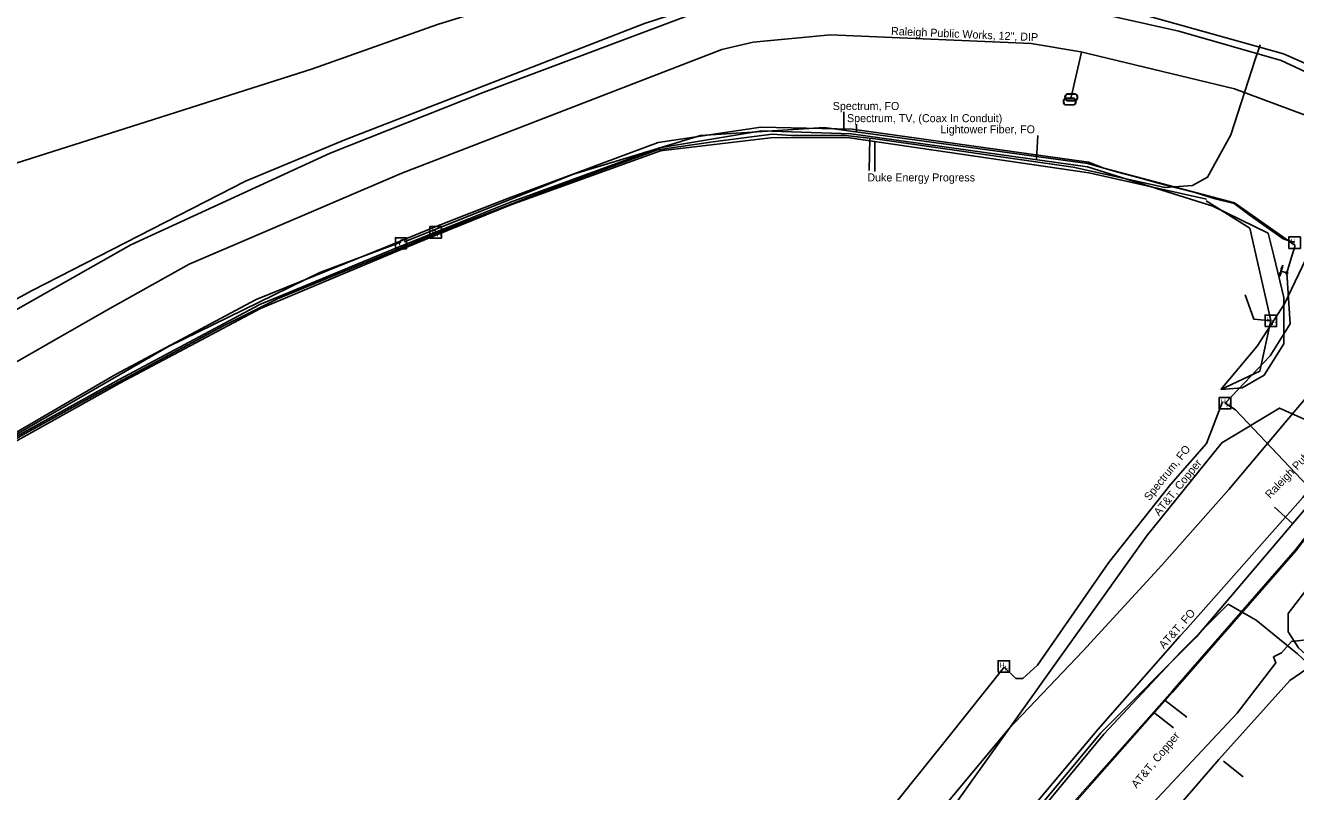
# Model space of a CAD drawing. Extents: x 2070721 to 2083039, y 729290 to 737883.
# Drawn here: x 2081248 to 2081883, y 734630 to 735013 of the extents above; entities that cross this region are included whole.
import ezdxf

# ---------------------------------------------------------------- set-up
doc = ezdxf.new("R2010")
doc.units = 0
for name, color, linetype in [('Cogo Default Point CELL', 7, 'Continuous'), ('Exist Utilities Gas UG Line SUE Cogo Point CELL', 7, 'Continuous'), ('Exist Utilities Gas UG Line SUE LOS B Cogo Comment', 7, 'Continuous'), ('Exist Utilities Gas UG Line SUE LOS B Cogo Number', 7, 'Continuous'), ('Exist Utilities Gas UG Line SUE LOS B Cogo Point CELL', 7, 'Continuous'), ('Exist Utilities Gas Valve CELL', 7, 'Continuous'), ('Exist Utilities Gas Valve Cogo Elevation', 7, 'Continuous'), ('Exist Utilities Other Unknown UG SUE Cogo Point CELL', 7, 'Continuous'), ('Exist Utilities Power Pole Cogo Elevation', 7, 'Continuous'), ('Exist Utilities Telephone UG Cable Cogo Point CELL', 7, 'Continuous'), ('Exist Utilities Telephone UG Cable SUE LOS C Cogo Comment', 7, 'Continuous'), ('Exist Utilities Telephone UG Cable SUE LOS C Cogo Elevation', 7, 'Continuous'), ('Exist Utilities Telephone UG FO Cogo Point CELL', 7, 'Continuous'), ('Exist Utilities Telephone UG FO SUE LOS B Cogo Number', 7, 'Continuous'), ('Exist Utilities TV Hand Hole CELL', 7, 'Continuous'), ('Exist Utilities TV Pedestal CELL', 7, 'Continuous'), ('Exist Utilities TV Pedestal Cogo Elevation', 7, 'Continuous'), ('Exist Utilities TV UG Cable Cogo Point CELL', 7, 'Continuous'), ('Exist Utilities TV UG Cable SUE LOS C Cogo Comment', 7, 'Continuous'), ('Exist Utilities TV UG Cable SUE LOS C Cogo Number', 7, 'Continuous'), ('Exist Utilities TV UG Cable SUE LOS C Cogo Point CELL', 7, 'Continuous'), ('Exist Utilities Water Manhole Cogo Elevation', 7, 'Continuous'), ('Exist Utilities Water Manhole Cogo Number', 7, 'Continuous'), ('Exist Utilities Water Meter CELL', 7, 'Continuous'), ('Exist Utilities Water Meter Cogo Number', 7, 'Continuous'), ('Exist Utilities Water UG Line SUE LOS B Cogo Elevation', 7, 'Continuous'), ('Exist Utilities Water UG Line SUE LOS B Cogo Number', 7, 'Continuous'), ('Exist Utilities Water Valve CELL', 7, 'Continuous')]:
    doc.layers.add(name, color=color, linetype=linetype)

msp = doc.modelspace()

# ---------------------------------------------------------------- linework, layer by layer
at = {"layer": 'Cogo Default Point CELL'}
msp.add_line((2081435.56, 734903.92), (2081435.56, 734903.92), dxfattribs=at)
msp.add_lwpolyline([(2081432.79, 734901.15), (2081438.33, 734901.15), (2081438.33, 734906.7), (2081432.79, 734906.7), (2081432.79, 734901.15)], dxfattribs=at)
at = {"layer": 'Exist Utilities Gas UG Line SUE LOS B Cogo Number'}
msp.add_line((2081656.86, 734960.96), (2081656.86, 734969.6), dxfattribs=at)
at = {"layer": 'Exist Utilities Gas Valve CELL'}
for p, q in [((2081669.9, 734956.32), (2081669.61, 734940.23)), ((2081672.4, 734954.58), (2081672.4, 734939.68)), ((2081846.67, 734645.35), (2081856.43, 734637.48))]:
    msp.add_line(p, q, dxfattribs=at)
at = {"layer": 'Exist Utilities Gas Valve Cogo Elevation'}
for p, q in [((2081811.7, 734669.77), (2081821.62, 734661.91)), ((2081817.5, 734675.55), (2081828.33, 734667.26))]:
    msp.add_line(p, q, dxfattribs=at)
at = {"layer": 'Exist Utilities Other Unknown UG SUE Cogo Point CELL'}
msp.add_line((2081663.14, 734959.52), (2081663.14, 734963.39), dxfattribs=at)
at = {"layer": 'Exist Utilities Power Pole Cogo Elevation'}
msp.add_lwpolyline([(2081225.5, 734796.32), (2081248.11, 734809.04), (2081287.63, 734830.88), (2081326.72, 734851.91), (2081347.2, 734862.89), (2081373.88, 734876.14), (2081398.46, 734886.3), (2081460.49, 734911.77), (2081509.14, 734930.55), (2081563.83, 734950.54), (2081592.79, 734954.64), (2081621.06, 734958.42), (2081630.74, 734957.65), (2081639.48, 734957.65), (2081657.7, 734957.65), (2081672.52, 734956.07), (2081771.45, 734941.91), (2081817.43, 734931.74), (2081831.08, 734932.73), (2081838.68, 734936.87), (2081850.29, 734958.08), (2081862.4, 734995.7), (2081864.93, 735002.95)], dxfattribs=at)
at = {"layer": 'Exist Utilities Telephone UG Cable Cogo Point CELL'}
for p, q in [((2081882.13, 734904.21), (2081882.13, 734904.21)), ((2081847.37, 734824.04), (2081847.37, 734824.04)), ((2081736.86, 734692.57), (2081736.86, 734692.57))]:
    msp.add_line(p, q, dxfattribs=at)
for points in [[(2081879.26, 734901.33), (2081885.01, 734901.33), (2081885.01, 734907.08), (2081879.26, 734907.08), (2081879.26, 734901.33)], [(2081844.5, 734821.17), (2081850.25, 734821.17), (2081850.25, 734826.92), (2081844.5, 734826.92), (2081844.5, 734821.17)], [(2081733.99, 734689.7), (2081739.74, 734689.7), (2081739.74, 734695.45), (2081733.99, 734695.45), (2081733.99, 734689.7)]]:
    msp.add_lwpolyline(points, dxfattribs=at)
at = {"layer": 'Exist Utilities Telephone UG Cable SUE LOS C Cogo Comment'}
msp.add_lwpolyline([(2081599.02, 734480.52), (2081638.91, 734537.92), (2081689.31, 734601.45), (2081739.23, 734661.21), (2081776.34, 734700.28), (2081815.77, 734743.2), (2081849.28, 734780.93), (2081877.42, 734814.37), (2081912.75, 734856.19), (2081950.81, 734928.53), (2081978.43, 734978.59)], dxfattribs=at)
at = {"layer": 'Exist Utilities Telephone UG Cable SUE LOS C Cogo Elevation'}
msp.add_line((2081870.31, 734865.04), (2081870.31, 734865.04), dxfattribs=at)
msp.add_lwpolyline([(2081867.36, 734862.32), (2081873.11, 734862.32), (2081873.11, 734868.07), (2081867.36, 734868.07), (2081867.36, 734862.32)], dxfattribs=at)
at = {"layer": 'Exist Utilities Telephone UG FO Cogo Point CELL'}
for p, q in [((2081769.76, 734974.66), (2081769.76, 734974.66)), ((2081770.56, 734976.78), (2081770.56, 734976.78))]:
    msp.add_line(p, q, dxfattribs=at)
for points in [[(2081767.72, 734976.36), (2081771.8, 734976.36)], [(2081767.72, 734976.22), (2081771.8, 734976.22)], [(2081772.6, 734975.22), (2081768.5, 734975.22)], [(2081772.6, 734975.08), (2081768.5, 734975.08)], [(2081768.52, 734978.48), (2081772.6, 734978.48)], [(2081768.52, 734978.34), (2081772.6, 734978.34)], [(2081771.8, 734973.1), (2081767.7, 734973.1)], [(2081771.8, 734972.96), (2081767.7, 734972.96)]]:
    msp.add_lwpolyline(points, dxfattribs=at)
for centre, radius, start, end in [((2081768.45, 734974.65), 1.86, 113.17804, 245.97939), ((2081768.46, 734974.65), 1.73, 115.30093, 243.78236), ((2081769.25, 734976.77), 1.86, 113.17804, 245.97939), ((2081769.26, 734976.77), 1.73, 115.30093, 243.78236), ((2081771.05, 734974.66), 1.86, 293.64832, 66.30838), ((2081771.06, 734974.66), 1.73, 295.12717, 64.87283), ((2081771.85, 734976.78), 1.86, 293.64832, 66.30838), ((2081771.86, 734976.78), 1.73, 295.12717, 64.87283)]:
    msp.add_arc(centre, radius, start, end, dxfattribs=at)
at = {"layer": 'Exist Utilities Telephone UG FO SUE LOS B Cogo Number'}
for p, q in [((2081450.05, 734912.23), (2081450.05, 734906.51)), ((2081455.77, 734912.23), (2081450.05, 734912.23)), ((2081455.77, 734906.51), (2081455.77, 734912.23)), ((2081450.05, 734906.51), (2081455.77, 734906.51)), ((2081452.91, 734909.37), (2081452.91, 734909.37))]:
    msp.add_line(p, q, dxfattribs=at)
at = {"layer": 'Exist Utilities TV Hand Hole CELL'}
msp.add_line((2081881.14, 734763.9), (2081872.17, 734772.1), dxfattribs=at)
at = {"layer": 'Exist Utilities TV Pedestal CELL'}
for points in [[(2081119.77, 734739.04), (2081129.02, 734745.24), (2081193.81, 734780.91), (2081230.47, 734802.17), (2081292.91, 734838.4), (2081363.18, 734875.86), (2081429.44, 734902.7), (2081451.9, 734911.7), (2081489.36, 734926.43), (2081564.05, 734954.16), (2081615.43, 734961.96), (2081661.12, 734960.94), (2081779.14, 734944.37)], [(2081779.14, 734944.37), (2081786.75, 734941.47), (2081852.08, 734924.1), (2081882.39, 734902.72)], [(2081878.3, 734889.11), (2081880.65, 734896.93), (2081882.39, 734902.72)], [(2081737.07, 734692.25), (2081742.78, 734686.66), (2081746.35, 734686.66), (2081753.66, 734693.25), (2081789.12, 734744.3), (2081820.35, 734783.54), (2081838.12, 734804), (2081846.1, 734824.65)], [(2081847.37, 734824.04), (2081852.66, 734820.72), (2081894.64, 734776.42), (2081923.55, 734738.76)], [(2081778.59, 734589.45), (2081774.62, 734600.43), (2081794.64, 734621.57), (2081803.63, 734616.23), (2081853.41, 734669.28), (2081872.71, 734694.38), (2081871.55, 734697.36), (2081875.65, 734699.45), (2081880.56, 734705.11), (2081892.44, 734706.39), (2081905.37, 734713.26), (2081917.92, 734727.97), (2081923.61, 734738.76)], [(2081622.95, 734557.31), (2081645.25, 734577.74), (2081708.9, 734656.89), (2081737.07, 734692.25)]]:
    msp.add_lwpolyline(points, dxfattribs=at)
at = {"layer": 'Exist Utilities TV Pedestal Cogo Elevation'}
msp.add_line((2081770.42, 734976.9), (2081775.58, 734999.35), dxfattribs=at)
for points in [[(2080902.52, 734692.58), (2081024.44, 734735.33), (2081064.65, 734749.07), (2081167.38, 734801.25), (2081288.56, 734870.47), (2081329.8, 734893.5), (2081435.94, 734938.99), (2081596, 735000.71), (2081611.53, 735004.3), (2081650.19, 735007.99), (2081750.43, 735003.6), (2081775.33, 734999.48), (2081852.16, 734980.94), (2081900.97, 734962.81), (2081973.29, 734925.34), (2081993.87, 734913.23), (2081994.94, 734912.69)], [(2081832.89, 734707.14), (2081836.89, 734711.88), (2081889.78, 734773.96), (2081955.02, 734857.75), (2081995.25, 734912.92), (2082019.91, 734949.11), (2082023.39, 734953.58)], [(2081545.19, 734320.14), (2081577.78, 734381.02), (2081631.24, 734467.17), (2081690.06, 734544.38), (2081695.68, 734551.66), (2081723.83, 734585.62), (2081785.29, 734659.45), (2081832.89, 734707.14)]]:
    msp.add_lwpolyline(points, dxfattribs=at)
at = {"layer": 'Exist Utilities TV UG Cable Cogo Point CELL'}
for points in [[(2080527.18, 734594.58), (2080756.63, 734677.7), (2080975.53, 734755.33), (2081114.85, 734806.49), (2081251.31, 734880.3), (2081357.91, 734934.96), (2081407.46, 734955.63), (2081557.34, 735013.56), (2081611.19, 735031.21), (2081670.8, 735036.79), (2081727.82, 735033.26), (2081796.62, 735020.83), (2081876.61, 734998.57), (2081913.61, 734982.12), (2081940.08, 734960.79), (2081955.36, 734908.6), (2081940.34, 734844.38), (2081917.15, 734795.51)], [(2080934.26, 734720.97), (2081041, 734761.39), (2081061.56, 734773.15), (2081150.65, 734813.71), (2081201.33, 734846.96), (2081300.64, 734903.05), (2081400.2, 734948.86), (2081476.71, 734979.23), (2081590.79, 735021.91), (2081620.53, 735029.68), (2081685.91, 735033.08), (2081745.92, 735027.46), (2081824.22, 735009.88), (2081875.43, 734995.15), (2081909.49, 734979.28), (2081909.49, 734966.35), (2081906.46, 734953.04)], [(2081845.25, 734830.92), (2081863.4, 734852.6), (2081877.12, 734873.61), (2081889.65, 734899.84)], [(2080953.21, 732796.69), (2081054.09, 733077.62), (2081111.09, 733245.57), (2081176.08, 733423.78), (2081231.97, 733580.28), (2081320.16, 733847.08), (2081418.84, 734093.09), (2081467.34, 734224.03), (2081494.06, 734287.2), (2081526.74, 734352.01), (2081556, 734404.62), (2081808.13, 734757.73), (2081845.73, 734804.26), (2081874.67, 734821.58), (2081898.66, 734810.94), (2081917.15, 734795.51)], [(2081675.15, 734515.17), (2081731.28, 734579.5), (2081761.87, 734613.73), (2081821.11, 734680.35), (2081882.55, 734750.91), (2081917.05, 734795.26)], [(2081675.44, 734514.41), (2081731.46, 734578.64), (2081762.11, 734613), (2081821.17, 734679.68), (2081882.84, 734750.34), (2081917.15, 734795.51)], [(2081890.41, 734734.05), (2081878.89, 734718.98), (2081878.89, 734709.84), (2081884.04, 734701.82), (2081898.12, 734689.22), (2081947.49, 734647.24)], [(2081671.19, 734518.01), (2081739, 734601.03), (2081786.76, 734658.83), (2081825.08, 734699.74), (2081848.94, 734723.65), (2081862.89, 734715.73), (2081883.59, 734698.93), (2081903.62, 734680.48), (2081932.44, 734654.41), (2081944.85, 734644.1)]]:
    msp.add_lwpolyline(points, dxfattribs=at)
at = {"layer": 'Exist Utilities TV UG Cable SUE LOS C Cogo Comment'}
for points in [[(2081128.97, 734740.08), (2081231.48, 734798.66), (2081295.17, 734834.12), (2081365.43, 734871.31), (2081433.71, 734899.92), (2081452.63, 734907.74), (2081490.45, 734923.08), (2081565.19, 734950.13), (2081621.73, 734956.73), (2081659.71, 734956.5), (2081779.27, 734939), (2081838.04, 734926)], [(2081845.21, 734830.86), (2081864.69, 734840.12), (2081870.23, 734865.29), (2081859.8, 734911.4), (2081837.99, 734925.16)], [(2081857.43, 734878.23), (2081861.69, 734866.04), (2081870.52, 734865.2)], [(2081747.02, 734534.16), (2081777.19, 734567.94), (2081814.78, 734612), (2081844.33, 734646.12), (2081879.78, 734685.51), (2081910.59, 734706.71), (2081931.49, 734737.7), (2081947.42, 734760.31), (2081973.14, 734786.73), (2081997.07, 734814.98), (2082022.89, 734845.44), (2082040.83, 734835.09)]]:
    msp.add_lwpolyline(points, dxfattribs=at)
at = {"layer": 'Exist Utilities TV UG Cable SUE LOS C Cogo Number'}
for points in [[(2081437.24, 734904.54), (2081521.81, 734938.42), (2081585.32, 734957.8), (2081647.07, 734961.7), (2081778.73, 734943.71)], [(2081778.73, 734943.71), (2081783.92, 734942.29), (2081793.79, 734939.4), (2081803.89, 734936.7), (2081813.54, 734934.08), (2081823.2, 734931.54), (2081832.91, 734929.03), (2081842.5, 734926.17), (2081851.98, 734923.76), (2081859.87, 734917.84), (2081867.93, 734912.05), (2081876.48, 734906.11), (2081882.13, 734904.21)], [(2081119.77, 734739.04), (2081129.13, 734744.58), (2081197.49, 734782.76), (2081230.42, 734801.16), (2081319.02, 734852.15), (2081394.96, 734889.39), (2081435.57, 734904.49)]]:
    msp.add_lwpolyline(points, dxfattribs=at)
at = {"layer": 'Exist Utilities TV UG Cable SUE LOS C Cogo Point CELL'}
for points in [[(2080898.17, 734842.61), (2080939.09, 734839.81), (2081012.97, 734869.95), (2081083.01, 734898.2), (2081127.31, 734908.53), (2081225.25, 734938.31), (2081315.55, 734966.89), (2081391.31, 734990.94), (2081453.77, 735013.11), (2081546.69, 735041.99), (2081598.87, 735063.2), (2081616.23, 735087.34), (2081634.46, 735137.35), (2081640.11, 735152.98), (2081692.01, 735167.85), (2081764.85, 735199.16), (2081820.69, 735222.51), (2081887.44, 735259.15), (2081965.65, 735305.42), (2082025.06, 735334.79), (2082065.42, 735359.68), (2082065.33, 735359.8), (2082125.22, 735390.95), (2082185.5, 735417.81)], [(2081099.85, 734724.62), (2081112.42, 734732.94), (2081128.56, 734742.73), (2081231.52, 734800.87), (2081294.72, 734835.92), (2081365.04, 734873.38), (2081431.01, 734900.6), (2081452.87, 734909.38), (2081490.35, 734924.36), (2081564.77, 734951.57), (2081615.8, 734959.97), (2081660.54, 734958.55), (2081778.72, 734942.12), (2081841.31, 734922.44), (2081868.96, 734908.94)], [(2081827.69, 734710.71), (2081886.29, 734776.88), (2081953.94, 734858.43), (2081991.01, 734909.31), (2082022.17, 734954.69)], [(2081542.88, 734322.62), (2081574.46, 734383.49), (2081629.3, 734469.05), (2081685.73, 734544.41), (2081784.03, 734661.28), (2081824.87, 734707.78), (2081827.69, 734710.71)]]:
    msp.add_lwpolyline(points, dxfattribs=at)
at = {"layer": 'Exist Utilities Water Manhole Cogo Elevation'}
msp.add_line((2081753.18, 734945.73), (2081753.87, 734957.67), dxfattribs=at)
at = {"layer": 'Exist Utilities Water UG Line SUE LOS B Cogo Elevation'}
msp.add_lwpolyline([(2081878.3, 734889.11), (2081879.9, 734863.62), (2081870, 734847.65), (2081847.37, 734824.04)], dxfattribs=at)
at = {"layer": 'Exist Utilities Water UG Line SUE LOS B Cogo Number'}
msp.add_lwpolyline([(2081845.48, 734830.94), (2081855.86, 734831.71), (2081866.94, 734838.07), (2081876.73, 734853.65), (2081876.73, 734876.9), (2081871.84, 734897.65), (2081868.96, 734908.94)], dxfattribs=at)
at = {"layer": 'Exist Utilities Water Valve CELL'}
for p, q in [((2081876.25, 734893), (2081874.53, 734887.29)), ((2081875.34, 734890), (2081876.25, 734893)), ((2081878.3, 734889.11), (2081875.34, 734890)), ((2081878.3, 734889.11), (2081878.3, 734889.11))]:
    msp.add_line(p, q, dxfattribs=at)
for points in [[(2081876.25, 734893), (2081876.01, 734891.02), (2081875.8, 734891.52), (2081875.4, 734891.24)], [(2081874.53, 734887.29), (2081874.77, 734889.28), (2081874.98, 734888.78), (2081875.38, 734889.06)]]:
    msp.add_lwpolyline(points, close=True, dxfattribs=at)
msp.add_circle((2081878.3, 734889.11), 0.517, dxfattribs=at)

# ---------------------------------------------------------------- texts
at = {"layer": 'Cogo Default Point CELL'}
msp.add_text('C', height=4, dxfattribs=at).set_placement((2081434.25, 734901.92))
at = {"layer": 'Exist Utilities Gas UG Line SUE Cogo Point CELL'}
for rotation, p in [(357.49234, (2081680.41, 735007.98)), (46.30747, (2081869.87, 734776.18))]:
    msp.add_text('Raleigh Public Works, 12", DIP ', height=4, rotation=rotation, dxfattribs=at).set_placement(p)
at = {"layer": 'Exist Utilities Gas UG Line SUE LOS B Cogo Comment'}
msp.add_text('Lightower Fiber, FO ', height=4, dxfattribs=at).set_placement((2081705.13, 734958.82))
msp.add_text('AT&T, FO', height=4, rotation=48.47133, dxfattribs=at).set_placement((2081816.88, 734701.07))
at = {"layer": 'Exist Utilities Gas UG Line SUE LOS B Cogo Point CELL'}
msp.add_text('Spectrum, FO', height=4, dxfattribs=at).set_placement((2081651.33, 734970.45))
msp.add_text('Spectrum, FO', height=4, rotation=51.48765, dxfattribs=at).set_placement((2081809.64, 734775.04))
at = {"layer": 'Exist Utilities Telephone UG Cable Cogo Point CELL'}
for p in [(2081880.04, 734903.56), (2081845.28, 734823.4), (2081847.86, 734821.94), (2081734.77, 734691.92), (2081737.35, 734690.46)]:
    msp.add_text('H', height=2.5, dxfattribs=at).set_placement(p)
at = {"layer": 'Exist Utilities Telephone UG Cable SUE LOS C Cogo Elevation'}
for p in [(2081868.15, 734864.57), (2081870.72, 734863.05)]:
    msp.add_text('H', height=2.5, dxfattribs=at).set_placement(p)
at = {"layer": 'Exist Utilities Telephone UG FO SUE LOS B Cogo Number'}
for p in [(2081450.83, 734908.78), (2081453.4, 734907.31)]:
    msp.add_text('H', height=2.5, dxfattribs=at).set_placement(p)
at = {"layer": 'Exist Utilities Water Manhole Cogo Number'}
msp.add_text('Spectrum, TV, (Coax In Conduit)', height=4, dxfattribs=at).set_placement((2081658.47, 734964.38))
at = {"layer": 'Exist Utilities Water Meter CELL'}
msp.add_text('Duke Energy Progress', height=4, dxfattribs=at).set_placement((2081668.64, 734934.78))
at = {"layer": 'Exist Utilities Water Meter Cogo Number'}
for rotation, p in [(51.06143, (2081814.47, 734767.46)), (50.42317, (2081803.18, 734631.49))]:
    msp.add_text('AT&T, Copper', height=4, rotation=rotation, dxfattribs=at).set_placement(p)

doc.saveas('drawing.dxf')
